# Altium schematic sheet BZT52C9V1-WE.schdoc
size 127 x 101 mm
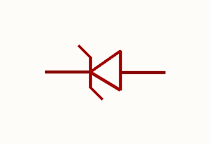
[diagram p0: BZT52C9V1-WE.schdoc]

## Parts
D?  bzt52c9v1_c364303  [SOD-123_L2.7-W1.6-LS3.7-RD-1]  (value not drawn)

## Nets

Not connected (* = marked no-connect by the designer): D? 1 2

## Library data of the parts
D? = bzt52c9v1_c364303: 二极管配置:1个独立式;稳压值(标称值):9.1V;稳压值(范围值):8.65V~9.5V;耗散功率(Pd):500mW;; Manufacturer: MDD(辰达半导体); Symbol: BZT52C9V1-WE; AddInBom: yes; ModelId: 528459655f7d4601a76356f3191c812b; ModelTransform: 151.575,66.929,0,0,0,0,0,0,0; Diode Configuration: 1个独立式; Zener Voltage(Nom): 9.1V; Reverse Leakage Current (Ir): 500nA@6V; Pd - Power Dissipation: 500mW; Impedance(Zzt): 30Ω; Tolerance: ±5%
